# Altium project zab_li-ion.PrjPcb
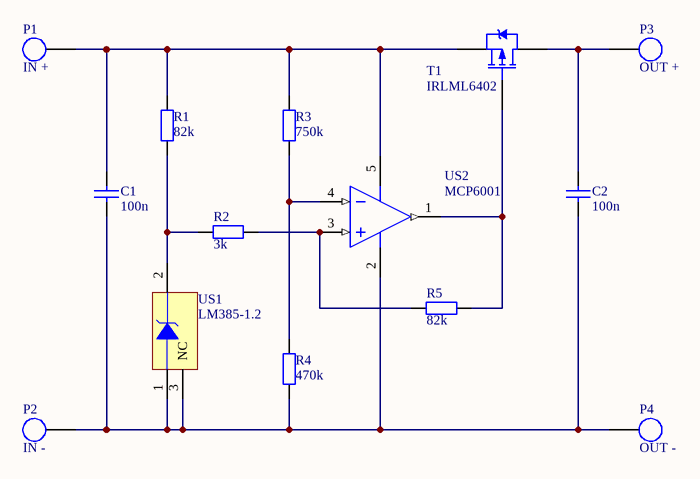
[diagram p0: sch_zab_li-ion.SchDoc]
1 sheet, 14 parts. Net scope: global (net labels, ports and power ports of the same name join across sheets).
Board file: pcb_zab_li-ion.PcbDoc

## Sheet sch_zab_li-ion.SchDoc
size A4

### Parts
C1  100n  [MELF-1206]
C2  100n  [MELF-1206]
P1  IN +  [pad fi 1mm]
P2  IN -  [pad fi 1mm]
P3  OUT +  [pad fi 1mm]
P4  OUT -  [pad fi 1mm]
R1  82k  [MELF-1206]
R2  3k  [MELF-1206]
R3  750k  [MELF-1206]
R4  470k  [MELF-1206]
R5  82k  [MELF-1206]
T1  IRLML6402  [SOT-23]
US1  LM385-1.2  [29-04]
US2  MCP6001  [SOT-23-OT5_N]

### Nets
NetC1_1: C1.1 C2.1 P2.1 P4.1 R4.2 US1.1(A) US1.3(NC) US2.2(VSS)
NetC1_2: C1.2 P1.1 R1.2 R3.2 T1.2(S) US2.5(VDD)
NetC2_2: C2.2 P3.1 T1.3(D)
NetR1_1: R1.1 R2.2 US1.2(K)
NetR2_1: R2.1 R5.1 US2.3(VIN+)
NetR3_1: R3.1 R4.1 US2.4(VIN-)
NetR5_2: R5.2 T1.1(G) US2.1(VOUT)

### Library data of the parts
C1 C2 = kondensator
P1-P4 = Pad
R1-R5 = rezystor
T1 = IRLML6302: HEXFET Power MOSFET
US1 = LM385BZ-1.2: Micropower Voltage Reference Diode
US2 = MCP6001T-E/OT: 1 MHz, Low-Power Operational Amplifier, 5-Pin SOT-23, Extended Temperature, Tape and Reel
